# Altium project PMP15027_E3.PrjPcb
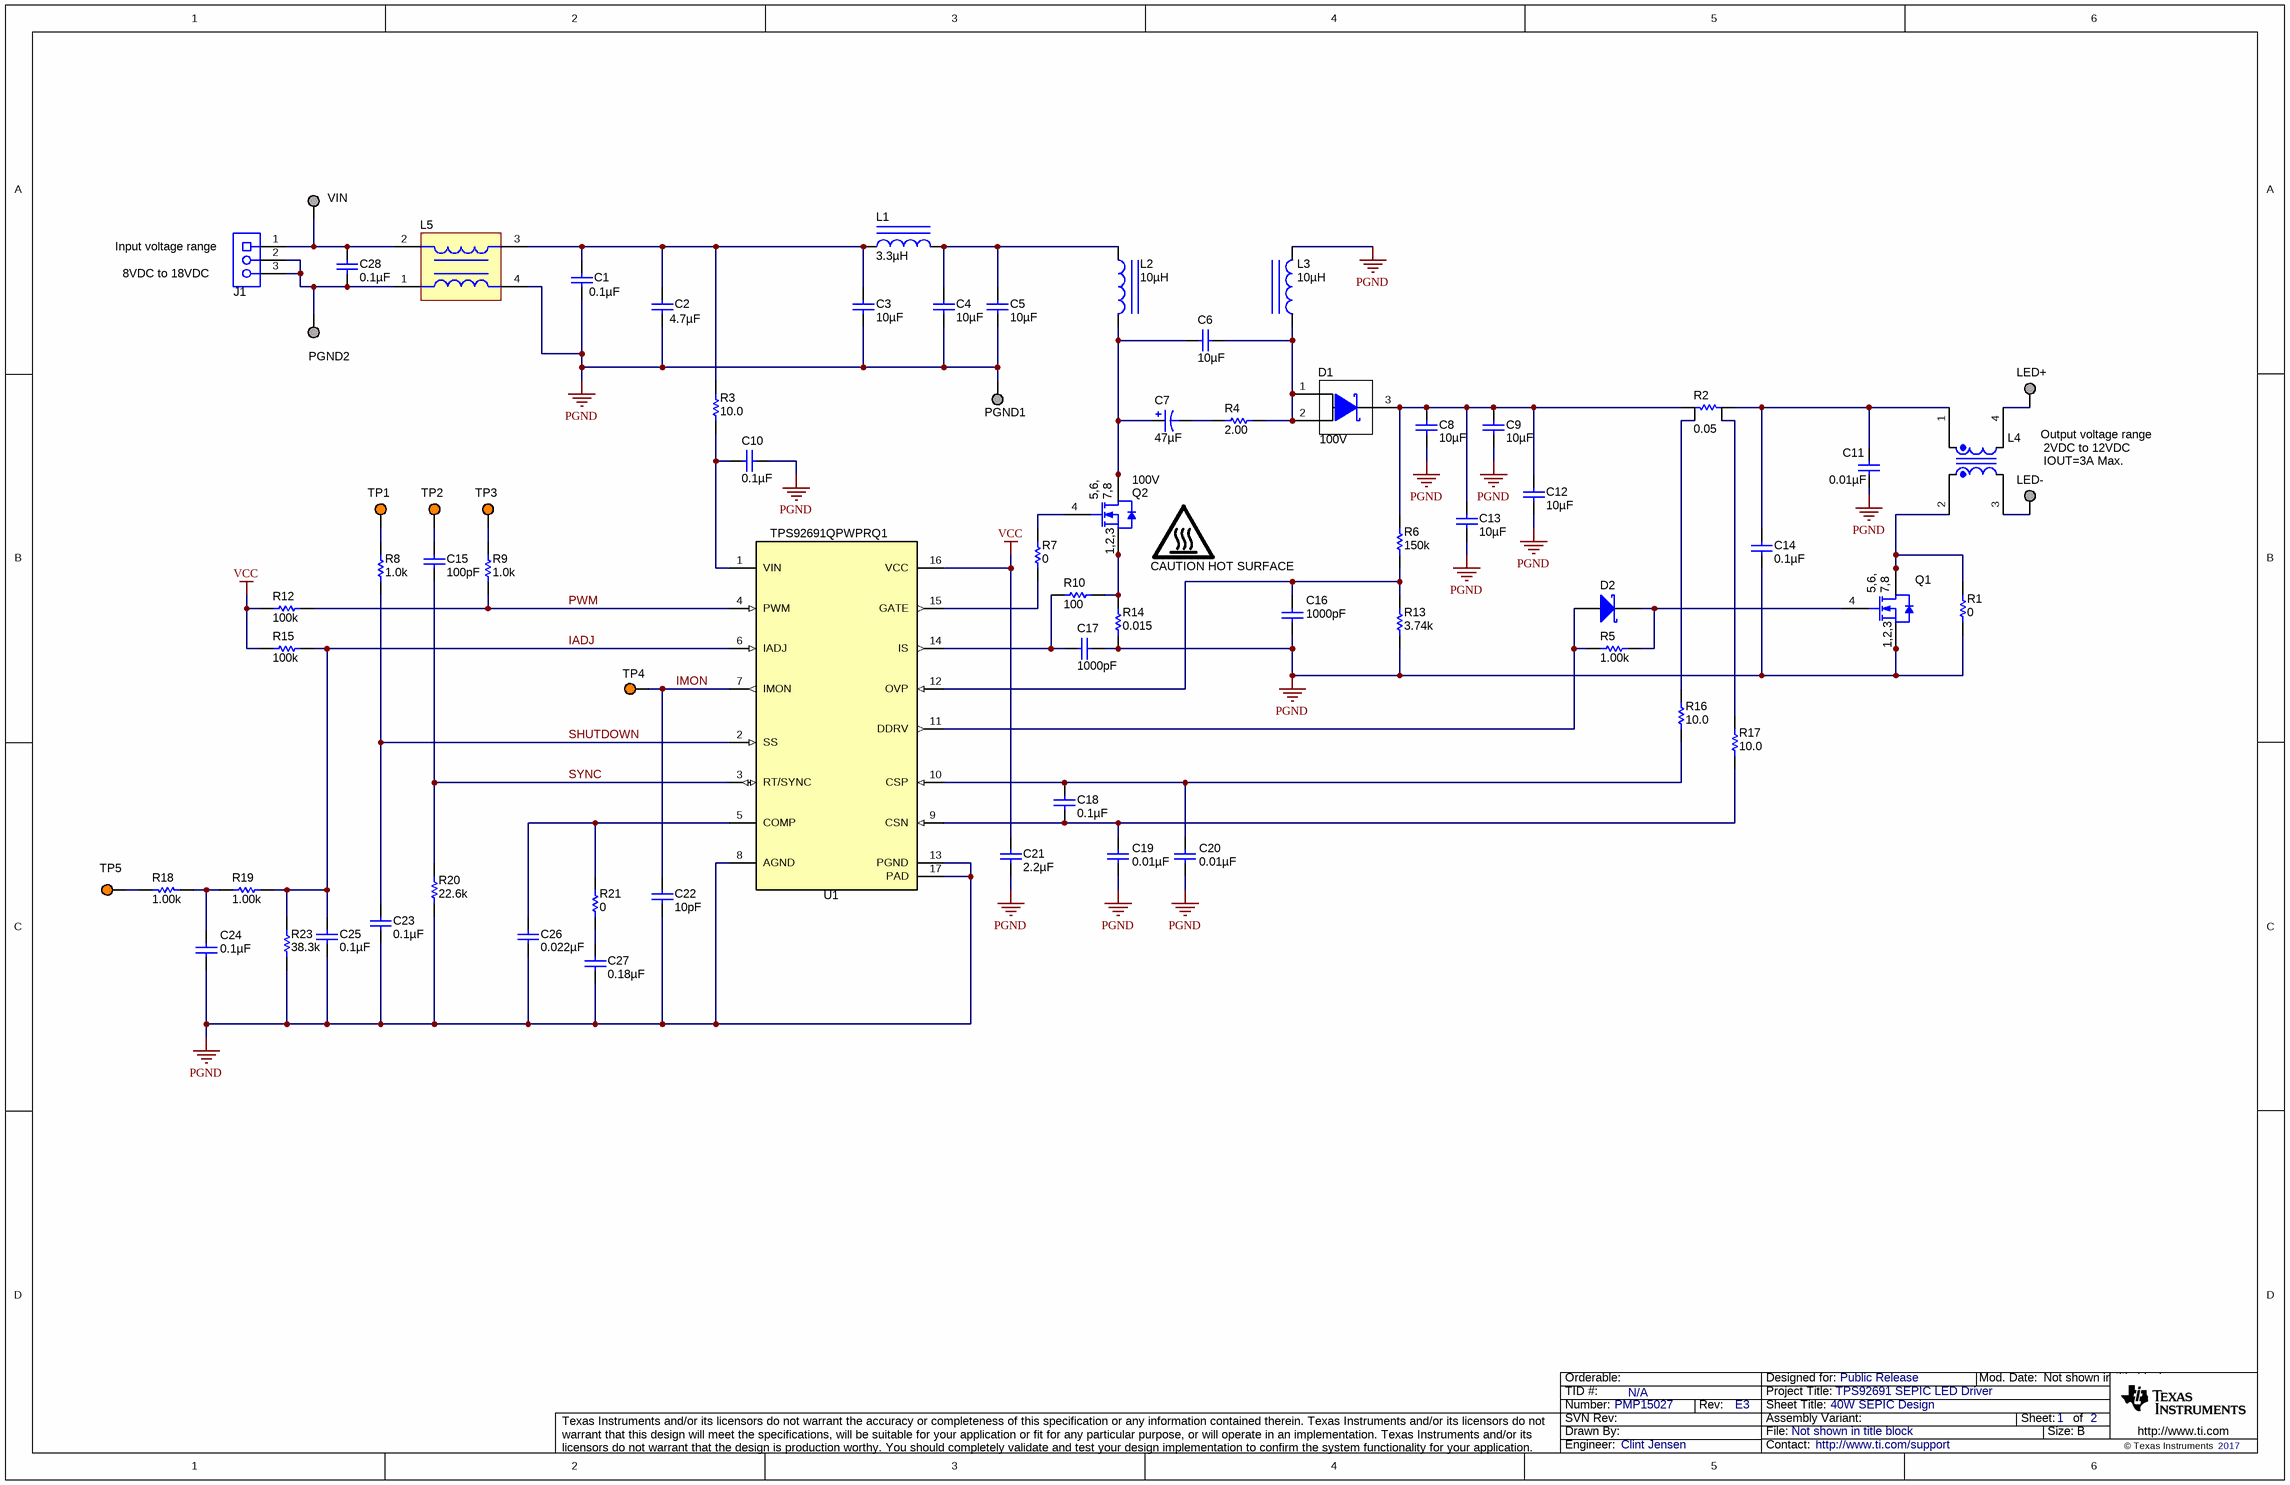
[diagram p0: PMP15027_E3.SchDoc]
TID: N/A; TechSupport: http://www.ti.com/support; SCH_Rev: E3; PRJ_Title: TPS92691 SEPIC LED Driver; PRJ_Number: PMP15027; PRJ_Engineer: Clint Jensen; PRJ_Customer: Public Release; PCB_Rev: E3; PCB_Layout: Kerry Murphy; CopyrightYear: 2017
2 sheets, 80 parts. Net scope: global (net labels, ports and power ports of the same name join across sheets).
Board file: PMP15027_E3.PcbDoc
Sheets:
  PMP15027_E3.SchDoc
  PMP15027_E3_Hardware.SchDoc

## Sheet PMP15027_E3.SchDoc: 40W SEPIC Design
size 431 x 279 mm; Date: Not shown in title block; ApprovedBy: Not shown in title block; CheckedBy: Not shown in title block; Author: Not shown in title block; CompanyName: Not shown in title block; Engineer: Not shown in title block; Organization: Not shown in title block; Address1: Not shown in title block; Address2: Not shown in title block; Address3: Not shown in title block; Address4: Not shown in title block; DocumentNumber: 1; Revision: Use project parameter SCH_Rev; SheetNumber: 1; SheetTotal: 2; PageSetup: Record=PageOptions¦CenterHorizontal=True¦CenterVertical=True¦PrintScale=1.00¦XCorrection=1.00¦YCorrection=1.00¦PrintKind=0¦BorderSize=5000000¦LeftOffset=0¦BottomOffset=0¦Orientation=2¦PaperLength=1000¦PaperWidth=1000¦Scale=100¦PaperSource=15¦PrintQuality=600¦MediaType=1¦DitherType=10¦PaperKind=Letter¦PrintScaleMode=1

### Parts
C1  ValueDisplayed: 0.1µF  [0805_HV]  (hidden comment: C2012X7R2A104K)
C2  ValueDisplayed: 4.7µF  [1210]  (hidden comment: C3225X7S2A475K200AE)
C3  ValueDisplayed: 10µF  [1210]  (hidden comment: CGA6P3X7S1H106K250AB)
C4  ValueDisplayed: 10µF  [1210]  (hidden comment: CGA6P3X7S1H106K250AB)
C5  ValueDisplayed: 10µF  [1210]  (hidden comment: CGA6P3X7S1H106K250AB)
C6  ValueDisplayed: 10µF  [1210]  (hidden comment: CGA6P3X7S1H106K250AB)
C7  ValueDisplayed: 47µF  [SM_RADIAL_D8]  (hidden comment: EEE-FK1H470XP)
C8  ValueDisplayed: 10µF  [1210]  (hidden comment: CGA6P3X7S1H106K250AB)
C9  ValueDisplayed: 10µF  [1210]  (hidden comment: CGA6P3X7S1H106K250AB)
C10  ValueDisplayed: 0.1µF  [0805_HV]  (hidden comment: C2012X7R2A104K)
C11  ValueDisplayed: 0.01µF  [0603_HV]  (hidden comment: C1608X8R2A103K)
C12  ValueDisplayed: 10µF  [1210]  (hidden comment: CGA6P3X7S1H106K250AB)
C13  ValueDisplayed: 10µF  [1210]  (hidden comment: CGA6P3X7S1H106K250AB)
C14  ValueDisplayed: 0.1µF  [1210]  (hidden comment: C1210C104K5RACTU)
C15  ValueDisplayed: 100pF  [0603_HV]  (hidden comment: C1608C0G1H101J)
C16  ValueDisplayed: 1000pF  [0603_HV]  (hidden comment: C1608C0G2A102J)
C17  ValueDisplayed: 1000pF  [0603_HV]  (hidden comment: C1608C0G2A102J)
C18  ValueDisplayed: 0.1µF  [0603_HV]  (hidden comment: GRM188R72A104KA35D)
C19  ValueDisplayed: 0.01µF  [0603_HV]  (hidden comment: C1608X8R2A103K)
C20  ValueDisplayed: 0.01µF  [0603_HV]  (hidden comment: C1608X8R2A103K)
C21  ValueDisplayed: 2.2µF  [0805_HV]  (hidden comment: C2012X7R1C225K)
C22  ValueDisplayed: 10pF  [0603_HV]  (hidden comment: C1608C0G1H100D)
C23  ValueDisplayed: 0.1µF  [0603_HV]  (hidden comment: C1608X8R1E104K)
C24  ValueDisplayed: 0.1µF  [0603_HV]  (hidden comment: C1608X8R1E104K)
C25  ValueDisplayed: 0.1µF  [0603_HV]  (hidden comment: C1608X8R1E104K)
C26  ValueDisplayed: 0.022µF  [0603_HV]  (hidden comment: GRM188R71C223KA01D)
C27  ValueDisplayed: 0.18µF  [0805_HV]  (hidden comment: GRM21BR71C184KA01L)
C28  ValueDisplayed: 0.1µF  [0805_HV]  (hidden comment: 08055C104JAT2A)
D1  value 100V  [TO-277A]  (hidden comment: FSV8100V)
D2  BAT54HT1G  [SOD-323]  (value not drawn)
J1  1727023  [Phoenix_1727023]  (value not drawn)
L1  ValueDisplayed: 3.3µH  [XAL6030]  (hidden comment: XAL6030-332MEB)
L2  ValueDisplayed: 10µH  [XAL1010]  (hidden comment: XAL1010-103MEB)
L3  ValueDisplayed: 10µH  [XAL1010]  (hidden comment: XAL1010-103MEB)
L4  ACM7060-701-2PL-TL01  [IND_TDK_ACM7060]  (value not drawn)
L5  ACM1211-102-2PL-TL01  [TDK_ACM1211]  (value not drawn)
LED+  Suggest using a net name here  [Keystone1502-2]  (value not drawn)
LED-  Suggest using a net name here  [Keystone1502-2]  (value not drawn)
LOGO4  CAUTION HOT SURFACE  [IEC_HotSurface_Small]  (no BOM)
PGND1  Suggest using a net name here  [Keystone1502-2]  (value not drawn)
PGND2  Suggest using a net name here  [Keystone1502-2]  (value not drawn)
Q1  STL8N10LF3  [PowerFLAT5x6_R]  (value not drawn)
Q2  value 100V  [PowerFLAT5x6_R]  (hidden comment: STL8N10LF3)
R1  ValueDisplayed: 0  [1206]  (hidden comment: CRCW12060000Z0EA)
R2  ValueDisplayed: 0.05  [LVK20]  (hidden comment: LVK20R050DER)
R3  ValueDisplayed: 10.0  [1206]  (hidden comment: CRCW120610R0FKEA)
R4  ValueDisplayed: 2.00  [1210]  (hidden comment: ERJ-14BQF2R0U)
R5  ValueDisplayed: 1.00k  [0603]  (hidden comment: CRCW06031K00FKEA)
R6  ValueDisplayed: 150k  [0603_HV]  (hidden comment: CRCW0603150KFKEA)
R7  ValueDisplayed: 0  [0603_HV]  (hidden comment: CRCW06030000Z0EA)
R8  ValueDisplayed: 1.0k  [0603_HV]  (hidden comment: CRCW06031K00JNEA)
R9  ValueDisplayed: 1.0k  [0603_HV]  (hidden comment: CRCW06031K00JNEA)
R10  ValueDisplayed: 100  [0603_HV]  (hidden comment: CRCW0603100RFKEA)
R12  ValueDisplayed: 100k  [0603_HV]  (hidden comment: CRCW0603100KFKEA)
R13  ValueDisplayed: 3.74k  [0603_HV]  (hidden comment: CRCW06033K74FKEA)
R14  ValueDisplayed: 0.015  [2010]  (hidden comment: CSRN2010FK15L0)
R15  ValueDisplayed: 100k  [0603_HV]  (hidden comment: CRCW0603100KFKEA)
R16  ValueDisplayed: 10.0  [0603_HV]  (hidden comment: CRCW060310R0FKEA)
R17  ValueDisplayed: 10.0  [0603_HV]  (hidden comment: CRCW060310R0FKEA)
R18  ValueDisplayed: 1.00k  [0603_HV]  (hidden comment: CRCW06031K00FKEA)
R19  ValueDisplayed: 1.00k  [0603_HV]  (hidden comment: CRCW06031K00FKEA)
R20  ValueDisplayed: 22.6k  [0603_HV]  (hidden comment: CRCW060322K6FKEA)
R21  ValueDisplayed: 0  [0603_HV]  (hidden comment: CRCW06030000Z0EA)
R23  ValueDisplayed: 38.3k  [0603]  (hidden comment: CRCW060338K3FKEA)
TP1  5003  [Keystone5003]  (value not drawn)
TP2  5003  [Keystone5003]  (value not drawn)
TP3  5003  [Keystone5003]  (value not drawn)
TP4  5003  [Keystone5003]  (value not drawn)
TP5  5003  [Keystone5003]  (value not drawn)
U1  TPS92691QPWPRQ1  [PWP0016J_N]
VIN  Suggest using a net name here  [Keystone1502-2]  (value not drawn)

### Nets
PGND: C1.2 C2.2 C3.2 C4.2 C5.2 C8.1 C9.1 C10.1 C11.2 C12.1 C13.1 C14.2 C16.2 C17.2 C19.2 C20.2 C21.2 C22.2 C23.2 C24.2 C25.2 C26.2 C27.1 L3.1 L5.4 PGND1.1 Q1.1(S) Q1.2(S) Q1.3(S) R1.1 R13.1 R14.1 R20.1 R23.1 U1.8(AGND) U1.13(PGND) U1.17(PAD)
VCC: C21.1 R12.1 R15.1 U1.16(VCC)
IADJ: C25.1 R15.2 R19.2 R23.2 U1.6(IADJ)
IMON: C22.1 TP4.1 U1.7(IMON)
PWM: R9.2 R12.2 U1.4(PWM)
SHUTDOWN: C23.1 R8.2 U1.2(SS)
SYNC: C15.1 R20.2 U1.3(RT/SYNC)
NetC1_1: C1.1 C2.1 C3.1 L1.1 L5.3 R3.2
NetC4_1: C4.1 C5.1 L1.2 L2.1
NetC6_1: C6.1 C7.1(+) L2.2 Q2.5(D) Q2.6(D) Q2.7(D) Q2.8(D) Q2.9(D)
NetC6_2: C6.2 D1.1(A) D1.2(A) L3.2 R4.2
NetC7_2: C7.2(-) R4.1
NetC8_2: C8.2 C9.2 C12.2 C13.2 D1.3(K) R2.1 R6.2
NetC10_2: C10.2 R3.1 U1.1(VIN)
NetC11_1: C11.1 C14.1 L4.1 R2.2
NetC15_2: C15.2 TP2.1
NetC16_1: C16.1 R6.1 R13.2 U1.12(OVP)
NetC17_1: C17.1 R10.1 U1.14(IS)
NetC18_1: C18.1 C20.1 R16.1 U1.10(CSP)
NetC18_2: C18.2 C19.1 R17.1 U1.9(CSN)
NetC24_1: C24.1 R18.2 R19.1
NetC26_1: C26.1 R21.2 U1.5(COMP)
NetC27_2: C27.2 R21.1
NetC28_1: C28.1 J1.1 L5.2 VIN.1
NetC28_2: C28.2 J1.2 J1.3 L5.1 PGND2.1
NetD2_1: D2.1(K) Q1.4(G) R5.2
NetD2_2: D2.2(A) R5.1 U1.11(DDRV)
NetL4_2: L4.2 Q1.5(D) Q1.6(D) Q1.7(D) Q1.8(D) Q1.9(D) R1.2
NetL4_3: L4.3 LED-.1
NetL4_4: L4.4 LED+.1
NetQ2_1: Q2.1(S) Q2.2(S) Q2.3(S) R10.2 R14.2
NetQ2_4: Q2.4(G) R7.2
NetR2_3: R2.3 R16.2
NetR2_4: R2.4 R17.2
NetR7_1: R7.1 U1.15(GATE)
NetR8_1: R8.1 TP1.1
NetR9_1: R9.1 TP3.1
NetR18_1: R18.1 TP5.1

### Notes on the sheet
- 8VDC to 18VDC
- (near J1) Input voltage range
- Output voltage range
- 2VDC to 12VDC
- IOUT=3A Max.

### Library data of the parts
C1 C10 = C2012X7R2A104K: CAP, CERM, 0.1 µF, 100 V, +/- 10%, X7R, 0805; Manufacturer: TDK; Polarized: N; CompType: Capacitor; Value: 0.1uF; U/M: EA; Cap_F: 0.0000001; Tolerance_%: 10; ESR_ohm: 0.0158; Value1: 0.0158 ohm; VDC_V: 100; Value2: 100V; TaMin_C: -55; TaMax_C: 125; Cap_Case: 0805
C2 = C3225X7S2A475K200AE: CAP, CERM, 4.7 µF, 100 V, +/- 10%, X7S, 1210; Manufacturer: TDK; Polarized: N; CompType: Capacitor; Value: 4.7uF; U/M: EA; Cap_F: 0.0000047; Tolerance_%: 10; Value1: Unknown; VDC_V: 100; Value2: 100V; TaMin_C: -55; TaMax_C: 125
C3-C6 C8 C9 C12 C13 = CGA6P3X7S1H106K250AB: CAP, CERM, 10 µF, 50 V, +/- 10%, X7S, AEC-Q200 Grade 1, 1210; Manufacturer: TDK; Polarized: N; CompType: Capacitor; Value: 10uF; U/M: EA; Cap_F: 0.00001; Tolerance_%: 10; ESR_ohm: 0.002827; Value1: 0.002827 ohm; VDC_V: 50; Value2: 50V; IRMS_A: 4.37286; TaMin_C: -55; TaMax_C: 125; Cap_Case: 1210_280; SizeArea_mm2: 8; SizeAreaWB_mm2: 14.7; SizeX_mm: 3.2; SizeY_mm: 2.5; SizeZ_mm: 2.8; AEC Category: Q200; AEC Qualified: Y; AEC Grade: 1
C7 = EEE-FK1H470XP: CAP, AL, 47 µF, 50 V, +/- 20%, 0.68 ohm, SMD; Manufacturer: Panasonic; Polarized: Y; CompType: Capacitor; Value: 47uF; U/M: EA; Cap_F: 0.000047; Tolerance_%: 20; ESR_ohm: 0.68; VDC_V: 50; Value2: 50V; IRMS_A: 0.195; TaMin_C: -55; TaMax_C: 105; Cap_Case: D8; AEC Category: Q200
C11 C19 C20 = C1608X8R2A103K: CAP, CERM, 0.01 µF, 100 V, +/- 10%, X8R, 0603; Manufacturer: TDK; Polarized: N; CompType: Capacitor; Value: 0.01uF; U/M: EA; Cap_F: 0.00000001; Tolerance_%: 10; ESR_ohm: 0.051; Value1: 0.051 ohm; VDC_V: 100; Value2: 100V; TaMin_C: -55; TaMax_C: 150; Cap_Case: 0603
C14 = C1210C104K5RACTU: CAP, CERM, 0.1 µF, 50 V, +/- 10%, X7R, 1210; Manufacturer: Kemet; Polarized: N; CompType: Capacitor; Value: 0.1uF; U/M: EA; Cap_F: 0.0000001; Tolerance_%: 10; Value1: Unknown; VDC_V: 50; Value2: 50V; TaMin_C: -55; TaMax_C: 125; AEC Category: Q200
C15 = C1608C0G1H101J: CAP, CERM, 100 pF, 50 V, +/- 5%, C0G/NP0, 0603; Manufacturer: TDK; Polarized: N; CompType: Capacitor; Value: 100pF; U/M: EA; Cap_F: 0.0000000001; Tolerance_%: 5; ESR_ohm: 0.1679; Value1: 0.1679 ohm; VDC_V: 50; Value2: 50V; TaMin_C: -55; TaMax_C: 125; Cap_Case: 0603
C16 C17 = C1608C0G2A102J: CAP, CERM, 1000 pF, 100 V, +/- 5%, C0G/NP0, 0603; Manufacturer: TDK; Polarized: N; CompType: Capacitor; Value: 1000pF; U/M: EA; Cap_F: 0.000000001; Tolerance_%: 5; ESR_ohm: 0.0589; Value1: 0.0589 ohm; VDC_V: 100; Value2: 100V; TaMin_C: -55; TaMax_C: 125; Cap_Case: 0603
C18 = GRM188R72A104KA35D: CAP, CERM, 0.1 µF, 100 V, +/- 10%, X7R, 0603; Manufacturer: MuRata; Polarized: N; CompType: Capacitor; Value: 0.1uF; U/M: EA; Cap_F: 0.0000001; Tolerance_%: 10; Value1: Unknown; VDC_V: 100; Value2: 100V; TaMin_C: -55; TaMax_C: 125; Cap_Case: 0603
C21 = C2012X7R1C225K: CAP, CERM, 2.2 µF, 16 V, +/- 10%, X7R, 0805; Manufacturer: TDK; Polarized: N; CompType: Capacitor; Value: 2.2uF; U/M: EA; Cap_F: 0.0000022; Tolerance_%: 10; ESR_ohm: 0.0049; Value1: 0.0049 ohm; VDC_V: 16; Value2: 16V; TaMin_C: -55; TaMax_C: 125; Cap_Case: 0805
C22 = C1608C0G1H100D: CAP, CERM, 10 pF, 50 V, +/- 5%, C0G/NP0, 0603; Manufacturer: TDK; Polarized: N; CompType: Capacitor; Value: 10pF; U/M: EA; Cap_F: 0.00000000001; Tolerance_%: 5; ESR_ohm: 0.3492; Value1: 0.3492 ohm; VDC_V: 50; Value2: 50V; TaMin_C: -55; TaMax_C: 125; Cap_Case: 0603
C23-C25 = C1608X8R1E104K: CAP, CERM, 0.1 µF, 25 V, +/- 10%, X8R, 0603; Manufacturer: TDK; Polarized: N; CompType: Capacitor; Value: 0.1uF; U/M: EA; Cap_F: 0.0000001; Tolerance_%: 10; ESR_ohm: 0.0131; Value1: 0.0131 ohm; VDC_V: 25; Value2: 25V; TaMin_C: -55; TaMax_C: 150; Cap_Case: 0603
C26 = GRM188R71C223KA01D: CAP, CERM, 0.022 µF, 16 V, +/- 10%, X7R, 0603; Manufacturer: MuRata; Polarized: N; CompType: Capacitor; Value: 0.022uF; U/M: EA; Cap_F: 0.000000022; Tolerance_%: 10; Value1: Unknown; VDC_V: 16; Value2: 16V; TaMin_C: -55; TaMax_C: 125; Cap_Case: 0603
C27 = GRM21BR71C184KA01L: CAP, CERM, 0.18 µF, 16 V, +/- 10%, X7R, 0805; Manufacturer: MuRata; Polarized: N; CompType: Capacitor; Value: 0.18uF; U/M: EA; Cap_F: 0.00000018; Tolerance_%: 10; Value1: Unknown; VDC_V: 16; Value2: 16V; TaMin_C: -55; TaMax_C: 125; Cap_Case: 0805; SizeArea_mm2: 2.5; SizeAreaWB_mm2: 6.75; SizeX_mm: 2; SizeY_mm: 1.25; SizeZ_mm: 1.45; AEC Category: Q200
C28 = 08055C104JAT2A: CAP, CERM, 0.1 µF, 50 V, +/- 5%, X7R, 0805; Manufacturer: AVX; Polarized: N; CompType: Capacitor; Value: 0.1uF; U/M: EA; Cap_F: 0.0000001; Tolerance_%: 5; ESR_ohm: 0.024; Value1: 0.024 ohm; VDC_V: 50; Value2: 50V; TaMin_C: -55; TaMax_C: 125; Cap_Case: 0805; SizeArea_mm2: 2.5; SizeAreaWB_mm2: 6.75; SizeX_mm: 2; SizeY_mm: 1.25; SizeZ_mm: 1.45; AEC Category: Q200
D1 = FSV8100V: Diode, Schottky, 100 V, 8 A, AEC-Q101, TO-277A; Manufacturer: Fairchild Semiconductor; U/M: EA; Vf_V: 0.67; Value1: 8A; Value2: 0.67V; Io_A: 8; Vr_V: 100; TJmax_C: 150; AEC Category: Q101; AEC Qualified: Y; SizeAreaWB_mm2: 56.1; SizeArea_mm2: 29.9; SizeX_mm: 4.6; SizeY_mm: 6.5; SizeZ_mm: 1.2
D2 = BAT54HT1G: Diode, Schottky, 30 V, 0.2 A, SOD-323; Manufacturer: ON Semiconductor; U/M: EA; Vf_V: 0.35; Value: 30V; Value1: 0.2A; Value2: 0.35V; Io_A: 0.2; Vr_V: 30; SizeAreaWB_mm2: 8.695; SizeArea_mm2: 3.645; SizeX_mm: 2.7; SizeY_mm: 1.35; SizeZ_mm: 1; AEC Category: Q101
J1 = 1727023: Terminal Block Receptacle, 3x1, 3.81mm, R/A, TH; Manufacturer: Phoenix Contact; SymbolCreator: a0412235; U/M: EA
L1 = XAL6030-332MEB: Inductor, Shielded, Composite, 3.3 µH, 9.8 A, 0.02 ohm, SMD; Manufacturer: Coilcraft; Value: 3.3uH; Ind_H: 3.3E-6; Imax_A: 9.8; Irms: 9.8A @ 40C rise; Isat: 12.2A @ 30% inductance drop; DCR_ohm: 0.02; Value2: 9.8A; SizeAreaWB_mm2: 71.5616; SizeArea_mm2: 41.7216; SizeX_mm: 6.36; SizeY_mm: 6.56; SizeZ_mm: 3.1; AEC Category: Q200
L2 L3 = XAL1010-103MEB: Inductor, Shielded, Composite, 10 µH, 15.5 A, 0.01 ohm, SMD; Manufacturer: Coilcraft; Value: 10uH; Ind_H: 10.0E-6; Imax_A: 15.5; Irms: 15.5A @ 40C rise; Isat: 17.5A @ 30% inductance drop; DCR_ohm: 0.01; Value2: 15.5A; AEC Category: Q200; SizeAreaWB_mm2: 159.6; SizeArea_mm2: 113; SizeX_mm: 11.3; SizeY_mm: 10
L4 = INDUCTOR_COUPLED: CMC 4A 2LN 700 OHM SMD; Manufacturer: TDK Corporation; CompType: Coupled Inductor; U/M: EA; Voltage Rating - DC: 80V; Filter Type: Power Line; DC Resistance (DCR) (Max): 15 mOhm; Number of Lines: 2; Impedance @ Frequency: 700 Ohm @ 100MHz
L5 = ACM1211-102-2PL-TL01: Coupled inductor, 6 A, 0.014 ohm, SMD; Manufacturer: TDK; SymbolCreator: Altium; DCR_ohm: 0.014
LED+ LED- PGND2 VIN = 1502-2: Terminal, Turret, TH, Double; Manufacturer: Keystone; CompType: Turret Terminal
LOGO4 = IEC_HotSurface: IEC 61010-1 Hot Surface Warning; SymbolCreator: a0412235
PGND1 = 1502-2: Terminal, Turret, TH, Double; Manufacturer: Keystone; CompType: Turret Terminal; U/M: EA
Q1 = STL8N10LF3: MOSFET, N-CH, 100 V, 20 A, AEC-Q101, 8-PowerVDFN; Manufacturer: STMicroelectronics; Alternate Manufacturer: None; U/M: EA; ChType: N; Value: 100V; VdsMax_V: 100; Value1: ? ohm; Value2: 20.5 nC; QgTyp_nC: 20.5; Vgs_V: 20; SizeAreaWB_mm2: 58.68; SizeArea_mm2: 31.98; SizeX_mm: 6.15; SizeY_mm: 5.2; SizeZ_mm: 1; AEC Category: Q101; AEC Qualified: Y
Q2 = STL8N10LF3: MOSFET, N-CH, 100 V, 20 A, AEC-Q101, 8-PowerVDFN; Manufacturer: STMicroelectronics; Alternate Manufacturer: None; U/M: EA; ChType: N; VdsMax_V: 100; Value1: ? ohm; Value2: 20.5 nC; QgTyp_nC: 20.5; Vgs_V: 20; AEC Category: Q101; AEC Qualified: Y
R1 = CRCW12060000Z0EA: RES, 0, 5%, 0.25 W, 1206; Manufacturer: Vishay-Dale; CompType: Resistor; Value: 0; Value_Code: 0000; Tolerance_%: 5; Power_W: 0.25; Value2: 0.25W; VDC_V: 200; TempCo: 200 ppm/C; SizeArea_mm2: 5.12; SizeX_mm: 3.2; SizeY_mm: 1.6; SizeZ_mm: 1.35; EIA_Code: E24; U/M: EA; AEC Category: Q200; Green_Lifecycle: Active; Green_REACh: Passed
R2 = LVK20R050DER: RES, 0.05, 0.5%, 0.75 W, 2010 sense; Manufacturer: Ohmite; CompType: Resistor; Value: 0.05; Value_Code: R050; Tolerance_%: 0.5; Power_W: 0.75; Value2: 0.75W; TempCo: 50 ppm/C; U/M: EA; AEC Category: Q200
R3 = CRCW120610R0FKEA: RES, 10.0, 1%, 0.25 W, 1206; Manufacturer: Vishay-Dale; CompType: Resistor; Value: 10.0; Res_ohm: 10; Value_Code: 10R0; Tolerance_%: 1; Power_W: 0.25; Value2: 0.25W; VDC_V: 200; TempCo: 100 ppm/C; EIA_Code: E96; U/M: EA
R4 = ERJ-14BQF2R0U: RES, 2.00, 1%, 0.5 W, AEC-Q200 Grade 0, 1210; Manufacturer: Panasonic; CompType: Resistor; Value: 2.00; Res_ohm: 2; Value_Code: 2R00; Tolerance_%: 1; Power_W: 0.5; Value2: 0.5W; TempCo: 100 ppm/C; EIA_Code: E96; U/M: EA; SizeArea_mm2: 8; SizeAreaWB_mm2: 14.7; SizeX_mm: 3.2; SizeY_mm: 2.5; SizeZ_mm: 1.35; AEC Category: Q200; AEC Qualified: Y; AEC Grade: 0
R5 = CRCW06031K00FKEA: RES, 1.00 k, 1%, 0.1 W, 0603; Manufacturer: Vishay-Dale; CompType: Resistor; Value: 1.00k; Res_ohm: 1000; Value_Code: 1k00; Tolerance_%: 1; Power_W: 0.1; Value2: 0.1W; VDC_V: 75; TempCo: 100 ppm/C; SizeArea_mm2: 1.28; SizeX_mm: 1.6; SizeY_mm: 0.8; EIA_Code: E96; U/M: EA; AEC Category: Q200
R6 = CRCW0603150KFKEA: RES, 150 k, 1%, 0.1 W, 0603; Manufacturer: Vishay-Dale; CompType: Resistor; Value: 150k; Res_ohm: 150000; Tolerance_%: 1; Power_W: 0.1; Value2: 0.1W; VDC_V: 75; TempCo: 100 ppm/C; EIA_Code: E96; U/M: EA; SizeArea_mm2: 1.28; SizeX_mm: 1.6; SizeY_mm: 0.8; AEC Category: Q200
R7 R21 = CRCW06030000Z0EA: RES, 0, 5%, 0.1 W, 0603; Manufacturer: Vishay-Dale; CompType: Resistor; Value: 0; Value_Code: 0000; Tolerance_%: 5; Power_W: 0.1; Value2: 0.1W; VDC_V: 75; TempCo: 200 ppm/C; EIA_Code: E24; U/M: EA; SizeArea_mm2: 1.28; SizeX_mm: 1.6; SizeY_mm: 0.8; SizeZ_mm: 1; AEC Category: Q200
R8 R9 = CRCW06031K00JNEA: RES, 1.0 k, 5%, 0.1 W, 0603; Manufacturer: Vishay-Dale; CompType: Resistor; Value: 1.0k; Res_ohm: 1000; Value_Code: 1k00; Tolerance_%: 5; Power_W: 0.1; Value2: 0.1W; VDC_V: 75; TempCo: 200 ppm/C; EIA_Code: E24; U/M: EA
R10 = CRCW0603100RFKEA: RES, 100, 1%, 0.1 W, 0603; Manufacturer: Vishay-Dale; CompType: Resistor; Value: 100; Value_Code: 100R; Tolerance_%: 1; Power_W: 0.1; Value2: 0.1W; VDC_V: 75; TempCo: 100 ppm/C; EIA_Code: E96; U/M: EA
R12 = CRCW0603100KFKEA: RES, 100 k, 1%, 0.1 W, 0603; Manufacturer: Vishay-Dale; CompType: Resistor; Value: 100k; Res_ohm: 100000; Tolerance_%: 1; Power_W: 0.1; Value2: 0.1W; VDC_V: 75; TempCo: 100 ppm/C; EIA_Code: E96; U/M: EA
R13 = CRCW06033K74FKEA: RES, 3.74 k, 1%, 0.1 W, 0603; Manufacturer: Vishay-Dale; CompType: Resistor; Value: 3.74k; Res_ohm: 3740; Value_Code: 3k74; Tolerance_%: 1; Power_W: 0.1; Value2: 0.1W; VDC_V: 75; TempCo: 100 ppm/C; EIA_Code: E96; U/M: EA; SizeArea_mm2: 1.28; SizeX_mm: 1.6; SizeY_mm: 0.8; AEC Category: Q200
R14 = CSRN2010FK15L0: RES, 0.015, 1%, 1 W, 2010; Manufacturer: Stackpole Electronics Inc; CompType: Resistor; Value: 0.015; Value_Code: R015; Tolerance_%: 1; Value2: 1W; TempCo: 250 ppm/C; EIA_Code: E96; U/M: EA; AEC Category: Q200
R15 = CRCW0603100KFKEA: RES, 100 k, 1%, 0.1 W, 0603; Manufacturer: Vishay-Dale; CompType: Resistor; Value: 100k; Res_ohm: 100000; Tolerance_%: 1; Power_W: 0.1; Value2: 0.1W; VDC_V: 75; TempCo: 100 ppm/C; EIA_Code: E96; U/M: EA; AEC Category: Q200; SizeArea_mm2: 1.28; SizeX_mm: 1.6; SizeY_mm: 0.8
R16 R17 = CRCW060310R0FKEA: RES, 10.0, 1%, 0.1 W, 0603; Manufacturer: Vishay-Dale; CompType: Resistor; Value: 10.0; Res_ohm: 10; Value_Code: 10R0; Tolerance_%: 1; Power_W: 0.1; Value2: 0.1W; VDC_V: 75; TempCo: 100 ppm/C; EIA_Code: E96; U/M: EA
R18 R19 = CRCW06031K00FKEA: RES, 1.00 k, 1%, 0.1 W, 0603; Manufacturer: Vishay-Dale; CompType: Resistor; Value: 1.00k; Res_ohm: 1000; Value_Code: 1k00; Tolerance_%: 1; Power_W: 0.1; Value2: 0.1W; VDC_V: 75; TempCo: 100 ppm/C; EIA_Code: E96; U/M: EA; SizeArea_mm2: 1.28; SizeX_mm: 1.6; SizeY_mm: 0.8; AEC Category: Q200
R20 = CRCW060322K6FKEA: RES, 22.6 k, 1%, 0.1 W, 0603; Manufacturer: Vishay-Dale; CompType: Resistor; Value: 22.6k; Res_ohm: 22600; Value_Code: 22k6; Tolerance_%: 1; Power_W: 0.1; Value2: 0.1W; VDC_V: 75; TempCo: 100 ppm/C; EIA_Code: E96; U/M: EA; SizeArea_mm2: 1.28; SizeX_mm: 1.6; SizeY_mm: 0.8; AEC Category: Q200
R23 = CRCW060338K3FKEA: RES, 38.3 k, 1%, 0.1 W, 0603; Manufacturer: Vishay-Dale; CompType: Resistor; Value: 38.3k; Res_ohm: 38300; Value_Code: 38k3; Tolerance_%: 1; Power_W: 0.1; Value2: 0.1W; VDC_V: 75; TempCo: 100 ppm/C; EIA_Code: E96; U/M: EA; AEC Category: Q200; SizeArea_mm2: 1.28; SizeX_mm: 1.6; SizeY_mm: 0.8
TP1-TP5 = 5003: Test Point, Miniature, Orange, TH; Manufacturer: Keystone; CompType: Test Point Loop; U/M: EA
U1 = TPS92691QPWPRQ1: Multi-Topology LED Driver with Rail-to-Rail Current Sense Amplifier, PWP0016J; Alternate PartNumber: TPS92691QPWPTQ1; Manufacturer: Texas Instruments; SymbolCreator: Altium; CompType: IC; U/M: EA

## Sheet PMP15027_E3_Hardware.SchDoc
size 431 x 279 mm; Date: Not shown in title block; ApprovedBy: Not shown in title block; CheckedBy: Not shown in title block; Author: Not shown in title block; CompanyName: Not shown in title block; Engineer: Not shown in title block; Organization: Not shown in title block; Address1: Not shown in title block; Address2: Not shown in title block; Address3: Not shown in title block; Address4: Not shown in title block; DocumentNumber: 1; Revision: Use project parameter SCH_Rev; SheetNumber: 3; SheetTotal: 3; PageSetup: Record=PageOptions¦CenterHorizontal=True¦CenterVertical=True¦PrintScale=1.00¦XCorrection=1.00¦YCorrection=1.00¦PrintKind=0¦BorderSize=5000000¦LeftOffset=0¦BottomOffset=0¦Orientation=2¦PaperLength=1000¦PaperWidth=1000¦Scale=100¦PaperSource=15¦PrintQuality=600¦MediaType=1¦DitherType=10¦PaperKind=Letter¦PrintScaleMode=1
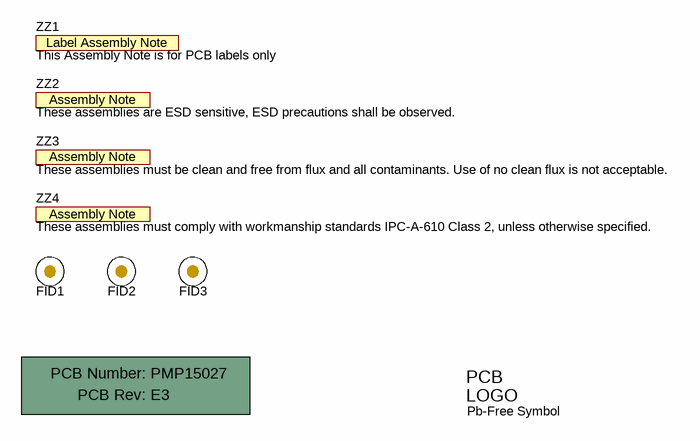
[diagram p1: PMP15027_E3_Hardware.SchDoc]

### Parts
!PCB  Printed Circuit Board  (value not drawn)  (mechanical)
FID1  Fiducial  [Fiducial10-20]  (value not drawn)
FID2  Fiducial  [Fiducial10-20]  (value not drawn)
FID3  Fiducial  [Fiducial10-20]  (value not drawn)
Logo2  Pb-Free Symbol  [Pb-Free_Overlay_Small]  (no BOM)
ZZ1  This Assembly Note is for PCB labels only  [AssemblyNoteLabel]  (no BOM)
ZZ2  These assemblies are ESD sensitive, ESD precautions shall be observed.  [AssemblyNote]  (no BOM)
ZZ3  These assemblies must be clean and free from flux and all contaminants. Use of no clean flux is not acceptable.  [AssemblyNote]  (no BOM)
ZZ4  These assemblies must comply with workmanship standards IPC-A-610 Class 2, unless otherwise specified.  [AssemblyNote]  (no BOM)

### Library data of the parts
!PCB = PCB: Manufacturer: Any; PartNumber: PMP15027; SymbolCreator: a0412235
FID1-FID3 = Fiducial: Fiducial mark.  There is nothing to buy or mount.; SymbolCreator: codlsc
Logo2 = Pb-Free: SymbolCreator: a0412235
ZZ1 = AssemblyNoteLabel: SymbolCreator: a0412235
ZZ2-ZZ4 = AssemblyNote: SymbolCreator: codlsc

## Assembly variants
001: not fitted FID1 FID2 FID3 R1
